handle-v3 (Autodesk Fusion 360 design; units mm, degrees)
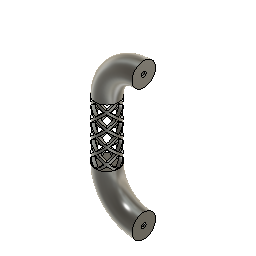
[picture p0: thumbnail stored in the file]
coil_primitive "CoilPrimitive1" Diameter 20 SectionSize 3 TaperAngle 0 Height 60 bodies "handle"
mirror "Mirror1" mirrorStitchTolerance 0.1
circular_pattern "C-Pattern1" TotalAngle 360
work_plane "WorkPlane1" AlongDistance 2
sketch "Sketch5" plane through (0, 0, 2) normal (0, 0, 1) x axis (1, 0, 0)
  line L1 (36.75, 13.1994) -> (36.75, -13.1994)
  line L2 (11.75, 13.2045) -> (11.75, -13.2045)
  circle C1 centre (0, 0) radius 11.75
  point P1 (0, 0)
  point P2 (0, 0)
  point P7 (11.75, 0)
  point P8 (36.75, 0)
  coincident P1 P2
  vertical L1
  vertical L2
  midpoint L2 P7
  horizontal P1 P7
  midpoint L1 P8
  horizontal P7 P8
  tangent C1 L2
  dimension "d11" diameter C1 = 23.5
  dimension "d13" distance L1 L2 = 25
combine "Combine1"
revolve "Revolve1" sketch "Sketch5" AlongAngle -90
work_plane "WorkPlane2"
work_plane "WorkPlane3"
sketch "Sketch7" plane through (36.75, 0, 0) normal (1, 0, 0) x axis (0, 1, 0)
  circle C1 centre (0, -34.75) radius 11.75
  circle C2 centre (0, -34.75) radius 1.35
  concentric C1 C2
  dimension "d17" diameter C2 = 2.7
extrude "Extrude1" cut sketch "Sketch7" profile of C2 against normal blind 17
chamfer "Chamfer1" distance 1
mirror "Mirror2" mirrorStitchTolerance 0.1
combine "Combine2"
named bodies: "handle"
